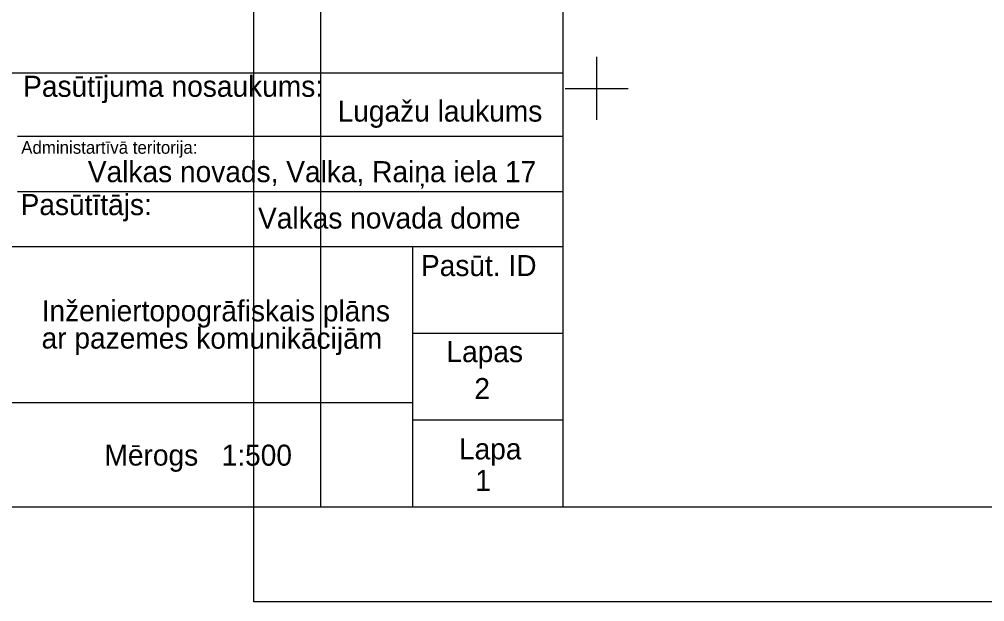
# Model space of a CAD drawing. Extents: x 619806 to 620082, y 405176 to 405386.
# Drawn here: x 619922.53 to 619968.46, y 405175.59 to 405203.29 of the extents above; entities that cross this region are included whole.
import ezdxf

# ---------------------------------------------------------------- set-up
doc = ezdxf.new("R2010")
doc.units = 0
doc.layers.add('GEOD_ELEM_####_####_#', color=7, linetype='Continuous')
doc.layers.add('RAMI_PLAN_####_TKST_#', color=7, linetype='Continuous')

msp = doc.modelspace()

# ---------------------------------------------------------------- linework, layer by layer
at = {"layer": 'GEOD_ELEM_####_####_#'}
for p, q in [((619950, 405201.5), (619950, 405200)), ((619948.5, 405200), (619950, 405200)), ((619950, 405200), (619950, 405198.5)), ((619950, 405200), (619951.5, 405200))]:
    msp.add_line(p, q, dxfattribs=at)
at = {"layer": 'RAMI_PLAN_####_TKST_#'}
for p, q in [((619922.45, 405197.734), (619948.393, 405197.734)), ((619948.394, 405197.548), (619948.393, 405180.095)), ((619922.45, 405195.102), (619948.393, 405195.102)), ((619948.393, 405192.47), (619885.54, 405192.47)), ((619941.241, 405192.47), (619941.241, 405180.095)), ((619948.393, 405188.348), (619941.241, 405188.348)), ((619941.241, 405185.045), (619885.54, 405185.045)), ((619948.393, 405184.226), (619941.241, 405184.226))]:
    msp.add_line(p, q, dxfattribs=at)
for points in [[(619933.685, 405385.595), (620082.185, 405385.595), (620082.185, 405175.595), (619933.685, 405175.595)], [(619805.793, 405180.095), (619805.793, 405373.209), (619948.393, 405373.209), (619948.393, 405180.095)], [(619936.885, 405180.095), (619936.885, 405373.209), (620079.485, 405373.209), (620079.485, 405180.095)], [(619885.54, 405200.734), (619948.393, 405200.734), (619948.393, 405180.095), (619885.54, 405180.095)]]:
    msp.add_lwpolyline(points, close=True, dxfattribs=at)

# ---------------------------------------------------------------- texts
for s, height, p in [('Pasūtījuma nosaukums:', 1, (619922.717, 405199.602)), ('Administartīvā teritorija:', 0.6, (619922.626, 405196.894)), ('Pasūt. ID', 1, (619941.644, 405191.078))]:
    msp.add_text(s, height=height, dxfattribs=at).set_placement(p)
for s, rotation, p in [('Lugažu laukums', 359.9999, (619937.678, 405198.423)), ('Valkas novads, Valka, Raiņa iela 17', 359.9999, (619925.794, 405195.542)), ('Pasūtītājs:', 359.9631, (619922.596, 405193.978)), ('Valkas novada dome', 359.9999, (619933.892, 405193.336)), ('Inženiertopogrāfiskais plāns', 359.9631, (619923.596, 405188.931)), ('ar pazemes komunikācijām', 359.9631, (619923.595, 405187.631)), ('Lapas', 359.9631, (619942.856, 405186.985)), ('2', 359.9631, (619944.183, 405185.229)), ('Mērogs   1:500', 359.9631, (619926.587, 405182.067)), ('Lapa', 359.9996, (619943.451, 405182.36)), ('1', 359.9996, (619944.228, 405180.862))]:
    msp.add_text(s, height=1, rotation=rotation, dxfattribs=at).set_placement(p)

doc.saveas('drawing.dxf')
